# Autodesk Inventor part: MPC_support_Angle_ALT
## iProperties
Shininess: 64.0
Length Units: 11269
Angle Units: 11279
Time Units: 11290
Mass Units: 11283
Length Display Precision: 3
Angle Display Precision: 2
Compacted: True
Part Number: MPC_support_Angle_ALT
Document SubType Name: Modeling
Created: 2004-08
Material: Aluminum-6061
Designer: John Blackburn
Manufacturer: Standard
Standards Organization: Custom
Density: 0.0
Volumn: 0.0
Area: 0.0
PropertySet Name: Model Information
Control State: 0
Master: False
Checked Out: False
Author: John Blackburn
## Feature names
1. Extrusion1
2. Chamfer1
3. Hole1
4. Extrusion2
5. Extrusion3
